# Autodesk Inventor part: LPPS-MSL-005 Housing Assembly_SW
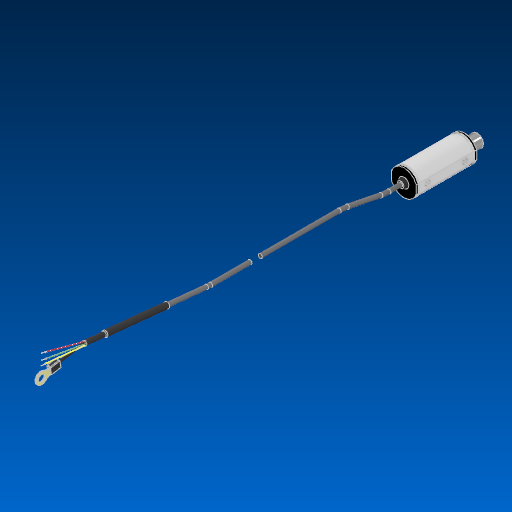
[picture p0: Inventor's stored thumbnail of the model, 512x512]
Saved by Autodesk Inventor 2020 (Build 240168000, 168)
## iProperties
Created: 2019-08
Part Number: LPPS-MSL-005 Housing Assembly_SW
Material: Generic
Document SubType Name: Modeling
Designer: J. Nielson
Density: 1 g/cm^3
Appearance: Default
Author: J. Nielson
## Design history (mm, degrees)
node "Assembly1"
body "Solid1"
node "Part1:1"
node "Part2:1"
body "Solid2"
node "Part3:1"
body "Solid3"
node "Part4:1"
body "Solid4"
node "Part5:1"
body "Solid5"
node "Part6:1"
body "Solid6"
node "Part7:1"
body "Solid7"
node "Part8:1"
body "Solid8"
node "Part9:1"
body "Solid9"
node "Part10:1"
body "Solid10"
node "Part11:1"
body "Solid11"
node "Part12:1"
body "Solid12"
node "Part13:1"
body "Solid13"
node "Part14:1"
body "Solid14"
node "Part15:1"
body "Solid15"
node "Part2:2"
body "Solid16"
node "Part2:3"
body "Solid17"
node "Part2:4"
body "Solid18"
node "Part16:1"
body "Solid19"
